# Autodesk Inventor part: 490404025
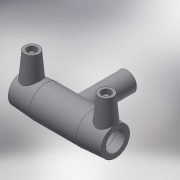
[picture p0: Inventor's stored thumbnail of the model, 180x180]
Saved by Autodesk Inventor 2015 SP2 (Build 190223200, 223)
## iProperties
Created: 2017-06
Part Number: 490404025
Material: Generic
Description: PLASSON TEE 25-25-25
Document SubType Name: Modeling
Designer: KIM
Mass: 57.3761 g
Surface Area: 241.06 cm^2
Volume: 57.3761 cm^3
Density: 1 g/cm^3
Appearance: Default
Author: KIM
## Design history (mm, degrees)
derived "490404.ipt"
feature "Solid1::490404.ipt"
tag "TaggingFeature1"
body "Solid1"
other parameters: "d0" = 103, "d1" = 25, "d2" = 44, "d3" = 39, "d4" = 25.75, "d5" = 39.6, "d6" = 23.75, "d7" = 25, "d8" = 168 deg, "d10" = 15.6, "d11" = 5.2, "d13" = 103, "d14" = 17.6296, "d17" = 22.5, "d18" = 25, "d19" = 3.52592, "d20" = 168 deg, "d22" = 40.92, "d23" = 44, "d24" = 39.6924, "d25" = 135 deg, "d26" = 72.1, "d27" = 135 deg, "d29" = 43, "d30" = 15, "d31" = 41.2, "d34" = 5 deg, "d35" = 15, "d39" = 5 deg, "d40" = 9.6, "d41" = 4.8, "d42" = 6, "d43" = 0, "d45" = 4, "d46" = 14, "d47" = 0, "d48" = -66, "d49" = 25, "d51" = 0, "d54" = 0, "d55" = 39.6, "d56" = 44, "d57" = 36.05, "d58" = 135 deg, "d59" = 39, "d60" = 39, "d61" = 135 deg, "d62" = 66, "d72" = 46.865, "d73" = 23.4325, "d74" = -66, "d75" = 26.25, "d77" = 0, "d80" = 0, "d81" = 25, "d82" = 44, "d83" = 0, "d84" = 3, "d85" = 0, "d86" = 3, "d87" = 0, "d88" = 11.31, "d89" = 2.8275, "d90" = 11.31, "d_" = 25, "L_" = 103, "L_1" = 39, "D_" = 44, "A_" = 43, "d_2" = 12, "H_" = 66
